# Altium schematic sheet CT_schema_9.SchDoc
size 308 x 210 mm
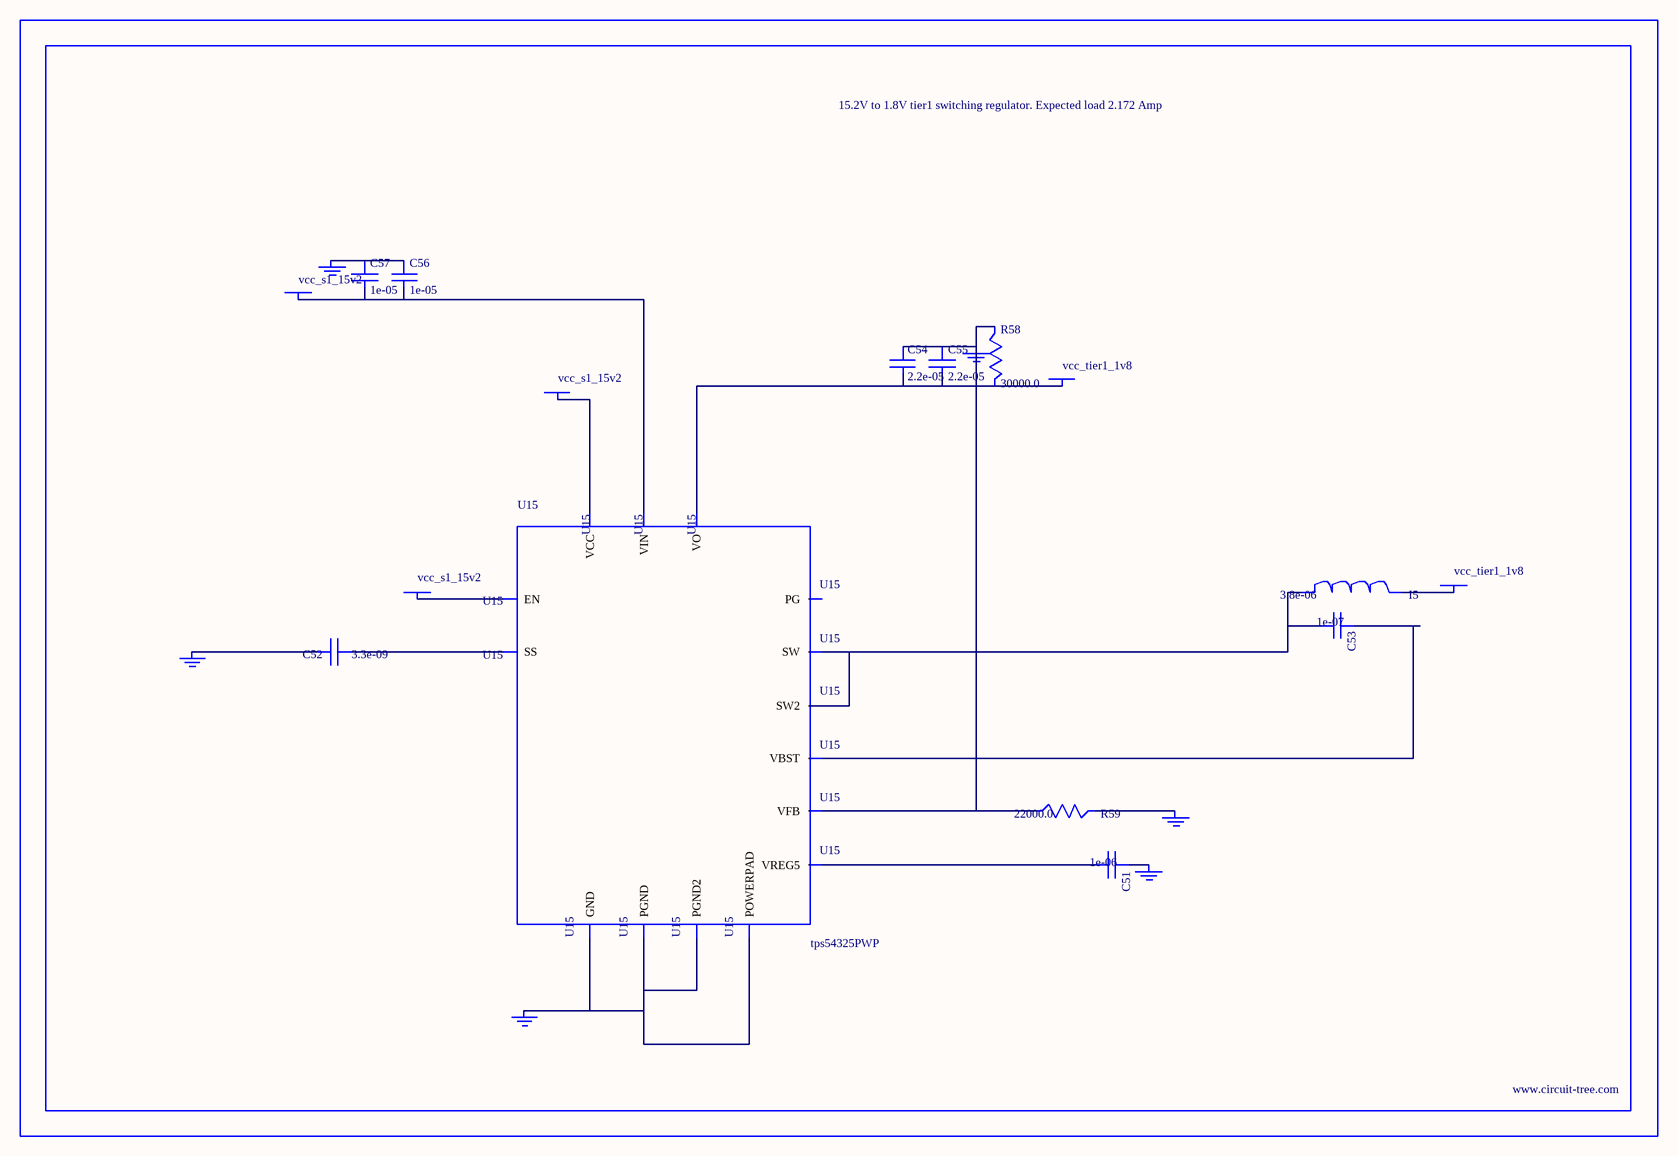
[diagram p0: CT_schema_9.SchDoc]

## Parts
BORDER8  (no value)
C51  1e-06  [C0603]
C52  3.3e-09  [C0402]
C53  1e-07  [C0402]
C54  2.2e-05  [C1210]
C55  2.2e-05  [C1210]
C56  1e-05  [C1206]
C57  1e-05  [C1206]
GND_INSTANCE_8_0  (no value)
GND_INSTANCE_8_1  (no value)
GND_INSTANCE_8_2  (no value)
GND_INSTANCE_8_3  (no value)
GND_INSTANCE_8_4  (no value)
GND_INSTANCE_8_5  (no value)
I5  3.8e-06  [DR1040]
POWER_INSTANCE_8_0  vcc_tier1_1v8
POWER_INSTANCE_8_1  vcc_s1_15v2
POWER_INSTANCE_8_2  vcc_tier1_1v8
POWER_INSTANCE_8_3  vcc_s1_15v2
POWER_INSTANCE_8_4  vcc_s1_15v2
R58  30000.0  [R0603]
R59  22000.0  [R0603]
U15  tps54325PWP  [HTSSOP14]

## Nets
NetC51_1: C51.1 GND_INSTANCE_8_2.0(GND)
NetC51_2: C51.2 U15.3(VREG5)
NetC52_1: C52.1 U15.4(SS)
NetC52_2: C52.2 GND_INSTANCE_8_3.0(GND)
NetC53_1: C53.1 U15.12(VBST)
NetC53_2: C53.2 I5.1 U15.10(SW) U15.11(SW2)
NetC54_1: C54.1 C55.1 GND_INSTANCE_8_0.0(GND) R58.1 R59.1 U15.2(VFB)
NetC54_2: C54.2 C55.2 POWER_INSTANCE_8_0.0(PWR) R58.2 U15.1(VO)
NetC56_1: C56.1 C57.1 GND_INSTANCE_8_5.0(GND)
NetC56_2: C56.2 C57.2 POWER_INSTANCE_8_3.0(PWR) U15.13(VIN)
NetGND_INSTANCE_8_1_0: GND_INSTANCE_8_1.0(GND) R59.2
NetGND_INSTANCE_8_4_0: GND_INSTANCE_8_4.0(GND) U15.5(GND) U15.8(PGND) U15.9(PGND2) U15.15(POWERPAD)
NetI5_2: I5.2 POWER_INSTANCE_8_2.0(PWR)
NetPOWER_INSTANCE_8_1_0: POWER_INSTANCE_8_1.0(PWR) U15.7(EN)
NetPOWER_INSTANCE_8_4_0: POWER_INSTANCE_8_4.0(PWR) U15.14(VCC)

Not connected (* = marked no-connect by the designer): U15 6(PG)

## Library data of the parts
BORDER8 = BORDER_PAGE8
C51 = C0603C105K3RACTU
C52 = C0402C332K3RAC
C53 = C0402C104K3RACTU
C54 C55 = GRM32ER61E226ME15L
C56 C57 = C1206C106K3RACTU
GND_INSTANCE_8_0-GND_INSTANCE_8_5 = GND
I5 = DR1040-3R8-R
POWER_INSTANCE_8_0-POWER_INSTANCE_8_4 = PWR
R58 = RC0603JR-0730KL
R59 = RC0603JR-0722KL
